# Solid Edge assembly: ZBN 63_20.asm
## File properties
Title: Zylinder
Author: bmolnar
Template: iso metric assembly.asm
Last saved by: bmolnar
Revision: 10
Application: Solid Edge
Username: bmolnar
Dokumentum tartalom típus: 1
Document Number: ZBN 63/20
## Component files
Profilrohr.par
Kolbenstange.par
Kit_2.par
Kit_1.par
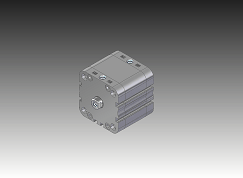
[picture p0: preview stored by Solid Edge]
